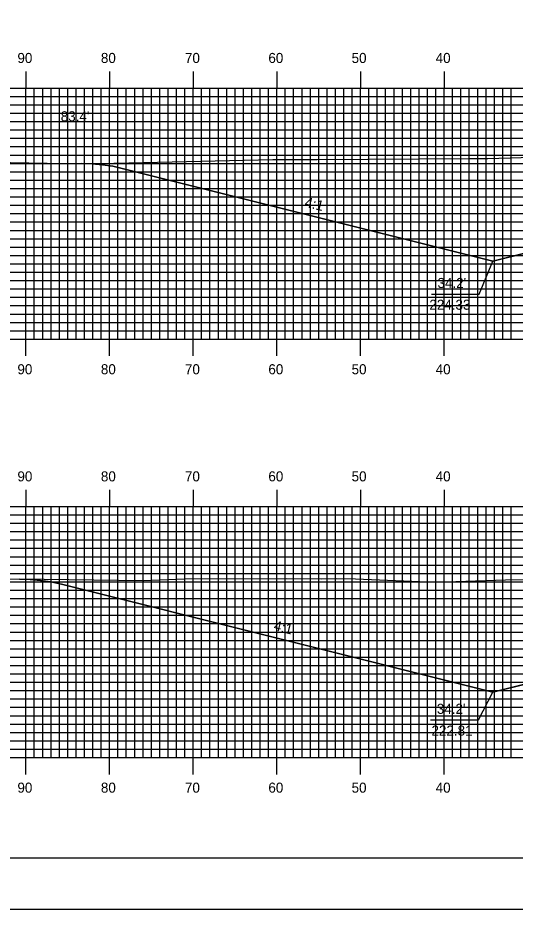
# Model space of a CAD drawing. Extents: x 1802716 to 1803060, y 442591 to 442811.
# Drawn here: x 1802791.1 to 1802850.6, y 442590.5 to 442697.1 of the extents above; entities that cross this region are included whole.
import ezdxf

# ---------------------------------------------------------------- set-up
doc = ezdxf.new("R2010")
doc.units = 0
for name, color, linetype in [('ANNOTATION', 7, 'Continuous'), ('BORDER', 7, 'Continuous'), ('D_Roadway_Centerline', 7, 'Continuous'), ('D_Roadway_SlopeLines', 7, 'Continuous'), ('D_Text_Standard', 7, 'Continuous'), ('H_V ANNOTATION', 7, 'Continuous'), ('MAJOR', 7, 'Continuous'), ('MINOR', 7, 'Continuous'), ('PLOT BOUNDARY', 7, 'Continuous'), ('S_Roadway_Centerline', 7, 'Continuous')]:
    doc.layers.add(name, color=color, linetype=linetype)

msp = doc.modelspace()

# ---------------------------------------------------------------- linework, layer by layer
at = {"layer": 'ANNOTATION'}
for points in [[(1802840.58, 442664.05), (1802846.27, 442664.05), (1802847.94, 442668)], [(1802840.49, 442613.16), (1802846.19, 442613.16), (1802847.94, 442616.48)]]:
    msp.add_lwpolyline(points, dxfattribs=at)
at = {"layer": 'BORDER'}
msp.add_lwpolyline([(1802732.51, 442596.67), (1803052.51, 442596.67), (1803052.51, 442806.67), (1802732.51, 442806.67)], close=True, dxfattribs=at)
at = {"layer": 'D_Roadway_Centerline'}
for points in [[(1802798.76, 442679.66), (1802800.01, 442679.63), (1802801.26, 442679.51), (1802802.51, 442679.32), (1802803.76, 442679.04), (1802847.94, 442668), (1802851.94, 442669), (1802862.11, 442671.54), (1802870.11, 442671.86), (1802882.11, 442672.1), (1802894.11, 442671.86), (1802902.11, 442671.54), (1802912.29, 442669), (1802916.29, 442668), (1802960.6, 442679.08), (1802961.85, 442679.35), (1802963.1, 442679.55), (1802964.35, 442679.68), (1802965.6, 442679.72)], [(1802791.35, 442630), (1802792.6, 442629.96), (1802793.85, 442629.84), (1802795.1, 442629.65), (1802796.35, 442629.37), (1802847.94, 442616.48), (1802851.94, 442617.48), (1802862.11, 442620.02), (1802870.11, 442620.34), (1802882.11, 442620.58), (1802894.11, 442620.34), (1802902.11, 442620.02), (1802912.29, 442617.48), (1802916.29, 442616.48), (1802968.41, 442629.51), (1802969.66, 442629.78), (1802970.91, 442629.97), (1802972.16, 442630.08), (1802973.41, 442630.1)]]:
    msp.add_lwpolyline(points, dxfattribs=at)
at = {"layer": 'D_Roadway_SlopeLines'}
for points in [[(1802847.94, 442668), (1802803.76, 442679.04), (1802802.51, 442679.32), (1802801.26, 442679.51), (1802800.01, 442679.63), (1802798.76, 442679.66)], [(1802862.11, 442671.54), (1802847.94, 442668)], [(1802847.94, 442616.48), (1802796.35, 442629.37), (1802795.1, 442629.65), (1802793.85, 442629.84), (1802792.6, 442629.96), (1802791.35, 442630)], [(1802862.11, 442620.02), (1802847.94, 442616.48)]]:
    msp.add_lwpolyline(points, dxfattribs=at)
at = {"layer": 'MAJOR'}
for p, q in [((1802792.11, 442690.67), (1802792.11, 442688.67)), ((1802802.11, 442690.67), (1802802.11, 442688.67)), ((1802812.11, 442690.67), (1802812.11, 442688.67)), ((1802822.11, 442690.67), (1802822.11, 442688.67)), ((1802832.11, 442690.67), (1802832.11, 442688.67)), ((1802842.11, 442690.67), (1802842.11, 442688.67)), ((1802742.11, 442688.67), (1803022.11, 442688.67)), ((1802742.11, 442688.67), (1803022.11, 442688.67)), ((1802792.11, 442658.67), (1802792.11, 442688.67)), ((1802802.11, 442658.67), (1802802.11, 442688.67)), ((1802812.11, 442658.67), (1802812.11, 442688.67)), ((1802822.11, 442658.67), (1802822.11, 442688.67)), ((1802832.11, 442658.67), (1802832.11, 442688.67)), ((1802842.11, 442658.67), (1802842.11, 442688.67)), ((1802742.11, 442683.67), (1803022.11, 442683.67)), ((1802742.11, 442678.67), (1803022.11, 442678.67)), ((1802742.11, 442673.67), (1803022.11, 442673.67)), ((1802742.11, 442668.67), (1803022.11, 442668.67)), ((1802742.11, 442663.67), (1803022.11, 442663.67)), ((1802742.11, 442658.67), (1803022.11, 442658.67)), ((1802742.11, 442658.67), (1803022.11, 442658.67)), ((1802792.11, 442656.66), (1802792.11, 442658.67)), ((1802802.11, 442656.66), (1802802.11, 442658.67)), ((1802812.11, 442656.66), (1802812.11, 442658.67)), ((1802822.11, 442656.66), (1802822.11, 442658.67)), ((1802832.11, 442656.66), (1802832.11, 442658.67)), ((1802842.11, 442656.66), (1802842.11, 442658.67)), ((1802792.11, 442640.67), (1802792.11, 442638.67)), ((1802802.11, 442640.67), (1802802.11, 442638.67)), ((1802812.11, 442640.67), (1802812.11, 442638.67)), ((1802822.11, 442640.67), (1802822.11, 442638.67)), ((1802832.11, 442640.67), (1802832.11, 442638.67)), ((1802842.11, 442640.67), (1802842.11, 442638.67)), ((1802742.11, 442638.67), (1803022.11, 442638.67)), ((1802742.11, 442638.67), (1803022.11, 442638.67)), ((1802792.11, 442608.67), (1802792.11, 442638.67)), ((1802802.11, 442608.67), (1802802.11, 442638.67)), ((1802812.11, 442608.67), (1802812.11, 442638.67)), ((1802822.11, 442608.67), (1802822.11, 442638.67)), ((1802832.11, 442608.67), (1802832.11, 442638.67)), ((1802842.11, 442608.67), (1802842.11, 442638.67)), ((1802742.11, 442633.67), (1803022.11, 442633.67)), ((1802742.11, 442628.67), (1803022.11, 442628.67)), ((1802742.11, 442623.67), (1803022.11, 442623.67)), ((1802742.11, 442618.67), (1803022.11, 442618.67)), ((1802742.11, 442613.67), (1803022.11, 442613.67)), ((1802742.11, 442608.67), (1803022.11, 442608.67)), ((1802742.11, 442608.67), (1803022.11, 442608.67)), ((1802792.11, 442606.66), (1802792.11, 442608.67)), ((1802802.11, 442606.66), (1802802.11, 442608.67)), ((1802812.11, 442606.66), (1802812.11, 442608.67)), ((1802822.11, 442606.66), (1802822.11, 442608.67)), ((1802832.11, 442606.66), (1802832.11, 442608.67)), ((1802842.11, 442606.66), (1802842.11, 442608.67))]:
    msp.add_line(p, q, dxfattribs=at)
at = {"layer": 'MINOR'}
for p, q in [((1802793.11, 442658.67), (1802793.11, 442688.67)), ((1802794.11, 442658.67), (1802794.11, 442688.67)), ((1802795.11, 442658.67), (1802795.11, 442688.67)), ((1802796.11, 442658.67), (1802796.11, 442688.67)), ((1802797.11, 442658.67), (1802797.11, 442688.67)), ((1802798.11, 442658.67), (1802798.11, 442688.67)), ((1802799.11, 442658.67), (1802799.11, 442688.67)), ((1802800.11, 442658.67), (1802800.11, 442688.67)), ((1802801.11, 442658.67), (1802801.11, 442688.67)), ((1802803.11, 442658.67), (1802803.11, 442688.67)), ((1802804.11, 442658.67), (1802804.11, 442688.67)), ((1802805.11, 442658.67), (1802805.11, 442688.67)), ((1802806.11, 442658.67), (1802806.11, 442688.67)), ((1802807.11, 442658.67), (1802807.11, 442688.67)), ((1802808.11, 442658.67), (1802808.11, 442688.67)), ((1802809.11, 442658.67), (1802809.11, 442688.67)), ((1802810.11, 442658.67), (1802810.11, 442688.67)), ((1802811.11, 442658.67), (1802811.11, 442688.67)), ((1802813.11, 442658.67), (1802813.11, 442688.67)), ((1802814.11, 442658.67), (1802814.11, 442688.67)), ((1802815.11, 442658.67), (1802815.11, 442688.67)), ((1802816.11, 442658.67), (1802816.11, 442688.67)), ((1802817.11, 442658.67), (1802817.11, 442688.67)), ((1802818.11, 442658.67), (1802818.11, 442688.67)), ((1802819.11, 442658.67), (1802819.11, 442688.67)), ((1802820.11, 442658.67), (1802820.11, 442688.67)), ((1802821.11, 442658.67), (1802821.11, 442688.67)), ((1802823.11, 442658.67), (1802823.11, 442688.67)), ((1802824.11, 442658.67), (1802824.11, 442688.67)), ((1802825.11, 442658.67), (1802825.11, 442688.67)), ((1802826.11, 442658.67), (1802826.11, 442688.67)), ((1802827.11, 442658.67), (1802827.11, 442688.67)), ((1802828.11, 442658.67), (1802828.11, 442688.67)), ((1802829.11, 442658.67), (1802829.11, 442688.67)), ((1802830.11, 442658.67), (1802830.11, 442688.67)), ((1802831.11, 442658.67), (1802831.11, 442688.67)), ((1802833.11, 442658.67), (1802833.11, 442688.67)), ((1802834.11, 442658.67), (1802834.11, 442688.67)), ((1802835.11, 442658.67), (1802835.11, 442688.67)), ((1802836.11, 442658.67), (1802836.11, 442688.67)), ((1802837.11, 442658.67), (1802837.11, 442688.67)), ((1802838.11, 442658.67), (1802838.11, 442688.67)), ((1802839.11, 442658.67), (1802839.11, 442688.67)), ((1802840.11, 442658.67), (1802840.11, 442688.67)), ((1802841.11, 442658.67), (1802841.11, 442688.67)), ((1802843.11, 442658.67), (1802843.11, 442688.67)), ((1802844.11, 442658.67), (1802844.11, 442688.67)), ((1802845.11, 442658.67), (1802845.11, 442688.67)), ((1802846.11, 442658.67), (1802846.11, 442688.67)), ((1802847.11, 442658.67), (1802847.11, 442688.67)), ((1802848.11, 442658.67), (1802848.11, 442688.67)), ((1802849.11, 442658.67), (1802849.11, 442688.67)), ((1802850.11, 442658.67), (1802850.11, 442688.67)), ((1802742.11, 442687.67), (1803022.11, 442687.67)), ((1802742.11, 442686.67), (1803022.11, 442686.67)), ((1802742.11, 442685.67), (1803022.11, 442685.67)), ((1802742.11, 442684.67), (1803022.11, 442684.67)), ((1802742.11, 442682.67), (1803022.11, 442682.67)), ((1802742.11, 442681.67), (1803022.11, 442681.67)), ((1802742.11, 442680.67), (1803022.11, 442680.67)), ((1802742.11, 442679.67), (1803022.11, 442679.67)), ((1802742.11, 442677.67), (1803022.11, 442677.67)), ((1802742.11, 442676.67), (1803022.11, 442676.67)), ((1802742.11, 442675.67), (1803022.11, 442675.67)), ((1802742.11, 442674.67), (1803022.11, 442674.67)), ((1802742.11, 442672.67), (1803022.11, 442672.67)), ((1802742.11, 442671.67), (1803022.11, 442671.67)), ((1802742.11, 442670.67), (1803022.11, 442670.67)), ((1802742.11, 442669.67), (1803022.11, 442669.67)), ((1802742.11, 442667.67), (1803022.11, 442667.67)), ((1802742.11, 442666.67), (1803022.11, 442666.67)), ((1802742.11, 442665.67), (1803022.11, 442665.67)), ((1802742.11, 442664.67), (1803022.11, 442664.67)), ((1802742.11, 442662.67), (1803022.11, 442662.67)), ((1802742.11, 442661.67), (1803022.11, 442661.67)), ((1802742.11, 442660.67), (1803022.11, 442660.67)), ((1802742.11, 442659.67), (1803022.11, 442659.67)), ((1802742.11, 442637.67), (1803022.11, 442637.67)), ((1802793.11, 442608.67), (1802793.11, 442638.67)), ((1802794.11, 442608.67), (1802794.11, 442638.67)), ((1802795.11, 442608.67), (1802795.11, 442638.67)), ((1802796.11, 442608.67), (1802796.11, 442638.67)), ((1802797.11, 442608.67), (1802797.11, 442638.67)), ((1802798.11, 442608.67), (1802798.11, 442638.67)), ((1802799.11, 442608.67), (1802799.11, 442638.67)), ((1802800.11, 442608.67), (1802800.11, 442638.67)), ((1802801.11, 442608.67), (1802801.11, 442638.67)), ((1802803.11, 442608.67), (1802803.11, 442638.67)), ((1802804.11, 442608.67), (1802804.11, 442638.67)), ((1802805.11, 442608.67), (1802805.11, 442638.67)), ((1802806.11, 442608.67), (1802806.11, 442638.67)), ((1802807.11, 442608.67), (1802807.11, 442638.67)), ((1802808.11, 442608.67), (1802808.11, 442638.67)), ((1802809.11, 442608.67), (1802809.11, 442638.67)), ((1802810.11, 442608.67), (1802810.11, 442638.67)), ((1802811.11, 442608.67), (1802811.11, 442638.67)), ((1802813.11, 442608.67), (1802813.11, 442638.67)), ((1802814.11, 442608.67), (1802814.11, 442638.67)), ((1802815.11, 442608.67), (1802815.11, 442638.67)), ((1802816.11, 442608.67), (1802816.11, 442638.67)), ((1802817.11, 442608.67), (1802817.11, 442638.67)), ((1802818.11, 442608.67), (1802818.11, 442638.67)), ((1802819.11, 442608.67), (1802819.11, 442638.67)), ((1802820.11, 442608.67), (1802820.11, 442638.67)), ((1802821.11, 442608.67), (1802821.11, 442638.67)), ((1802823.11, 442608.67), (1802823.11, 442638.67)), ((1802824.11, 442608.67), (1802824.11, 442638.67)), ((1802825.11, 442608.67), (1802825.11, 442638.67)), ((1802826.11, 442608.67), (1802826.11, 442638.67)), ((1802827.11, 442608.67), (1802827.11, 442638.67)), ((1802828.11, 442608.67), (1802828.11, 442638.67)), ((1802829.11, 442608.67), (1802829.11, 442638.67)), ((1802830.11, 442608.67), (1802830.11, 442638.67)), ((1802831.11, 442608.67), (1802831.11, 442638.67)), ((1802833.11, 442608.67), (1802833.11, 442638.67)), ((1802834.11, 442608.67), (1802834.11, 442638.67)), ((1802835.11, 442608.67), (1802835.11, 442638.67)), ((1802836.11, 442608.67), (1802836.11, 442638.67)), ((1802837.11, 442608.67), (1802837.11, 442638.67)), ((1802838.11, 442608.67), (1802838.11, 442638.67)), ((1802839.11, 442608.67), (1802839.11, 442638.67)), ((1802840.11, 442608.67), (1802840.11, 442638.67)), ((1802841.11, 442608.67), (1802841.11, 442638.67)), ((1802843.11, 442608.67), (1802843.11, 442638.67)), ((1802844.11, 442608.67), (1802844.11, 442638.67)), ((1802845.11, 442608.67), (1802845.11, 442638.67)), ((1802846.11, 442608.67), (1802846.11, 442638.67)), ((1802847.11, 442608.67), (1802847.11, 442638.67)), ((1802848.11, 442608.67), (1802848.11, 442638.67)), ((1802849.11, 442608.67), (1802849.11, 442638.67)), ((1802850.11, 442608.67), (1802850.11, 442638.67)), ((1802742.11, 442636.67), (1803022.11, 442636.67)), ((1802742.11, 442635.67), (1803022.11, 442635.67)), ((1802742.11, 442634.67), (1803022.11, 442634.67)), ((1802742.11, 442632.67), (1803022.11, 442632.67)), ((1802742.11, 442631.67), (1803022.11, 442631.67)), ((1802742.11, 442630.67), (1803022.11, 442630.67)), ((1802742.11, 442629.67), (1803022.11, 442629.67)), ((1802742.11, 442627.67), (1803022.11, 442627.67)), ((1802742.11, 442626.67), (1803022.11, 442626.67)), ((1802742.11, 442625.67), (1803022.11, 442625.67)), ((1802742.11, 442624.67), (1803022.11, 442624.67)), ((1802742.11, 442622.67), (1803022.11, 442622.67)), ((1802742.11, 442621.67), (1803022.11, 442621.67)), ((1802742.11, 442620.67), (1803022.11, 442620.67)), ((1802742.11, 442619.67), (1803022.11, 442619.67)), ((1802742.11, 442617.67), (1803022.11, 442617.67)), ((1802742.11, 442616.67), (1803022.11, 442616.67)), ((1802742.11, 442615.67), (1803022.11, 442615.67)), ((1802742.11, 442614.67), (1803022.11, 442614.67)), ((1802742.11, 442612.67), (1803022.11, 442612.67)), ((1802742.11, 442611.67), (1803022.11, 442611.67)), ((1802742.11, 442610.67), (1803022.11, 442610.67)), ((1802742.11, 442609.67), (1803022.11, 442609.67))]:
    msp.add_line(p, q, dxfattribs=at)
at = {"layer": 'PLOT BOUNDARY'}
msp.add_lwpolyline([(1802716.33, 442590.55), (1803056.33, 442590.55), (1803056.33, 442810.55), (1802716.33, 442810.55)], close=True, dxfattribs=at)
at = {"layer": 'S_Roadway_Centerline'}
for points in [[(1802783.65, 442679.88), (1802796.84, 442679.67), (1802800.81, 442679.66), (1802804.41, 442679.75), (1802821.62, 442680.14), (1802826.92, 442680.14), (1802845.1, 442680.24), (1802846.8, 442680.25), (1802847.32, 442680.25), (1802853.97, 442680.45), (1802867.66, 442679.87), (1802872.98, 442679.77), (1802882.61, 442679.93), (1802890.06, 442679.8), (1802900.48, 442679.63), (1802906.38, 442679.54), (1802911.28, 442679.52), (1802917.62, 442679.58)], [(1802784.94, 442630.01), (1802794.27, 442630), (1802806.15, 442629.83), (1802806.17, 442629.83), (1802806.19, 442629.83), (1802811.07, 442630.01), (1802823.21, 442630.08), (1802827.43, 442630.03), (1802829.19, 442630.06), (1802831.5, 442630.02), (1802841.11, 442629.61), (1802849.45, 442629.92), (1802857.32, 442629.95), (1802869.9, 442629.85), (1802882.79, 442629.54), (1802887.31, 442629.49), (1802891.97, 442629.26), (1802899.68, 442629.28), (1802908.42, 442629.62), (1802912.36, 442629.71), (1802922.39, 442629.64)]]:
    msp.add_lwpolyline(points, dxfattribs=at)

# ---------------------------------------------------------------- texts
at = {"layer": 'ANNOTATION'}
for p in [(1802825.36, 442674.51), (1802821.65, 442623.91)]:
    msp.add_text('4:1', height=1.2, rotation=345.9638, dxfattribs=at).set_placement(p)
for s, p in [("34.2'", (1802841.31, 442664.78)), ('224.33', (1802840.34, 442662.18)), ("34.2'", (1802841.23, 442613.89)), ('222.81', (1802840.59, 442611.29))]:
    msp.add_text(s, height=1.2, dxfattribs=at).set_placement(p)
at = {"layer": 'D_Text_Standard'}
msp.add_text("83.4'", height=1.2, dxfattribs=at).set_placement((1802796.27, 442684.7))
at = {"layer": 'H_V ANNOTATION'}
for s, p in [('90', (1802791.09, 442691.67)), ('80', (1802801.07, 442691.67)), ('70', (1802811.12, 442691.67)), ('60', (1802821.09, 442691.67)), ('50', (1802831.04, 442691.67)), ('40', (1802841.09, 442691.67)), ('90', (1802791.09, 442654.47)), ('80', (1802801.07, 442654.47)), ('70', (1802811.12, 442654.47)), ('60', (1802821.09, 442654.47)), ('50', (1802831.04, 442654.47)), ('40', (1802841.09, 442654.47)), ('90', (1802791.09, 442641.67)), ('80', (1802801.07, 442641.67)), ('70', (1802811.12, 442641.67)), ('60', (1802821.09, 442641.67)), ('50', (1802831.04, 442641.67)), ('40', (1802841.09, 442641.67)), ('90', (1802791.09, 442604.47)), ('80', (1802801.07, 442604.47)), ('70', (1802811.12, 442604.47)), ('60', (1802821.09, 442604.47)), ('50', (1802831.04, 442604.47)), ('40', (1802841.09, 442604.47))]:
    msp.add_text(s, height=1.2, dxfattribs=at).set_placement(p)

doc.saveas('drawing.dxf')
